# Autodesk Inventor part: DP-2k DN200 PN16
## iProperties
Created: 2009-08
Part Number: DP-2k DN200 PN16
Document SubType Name: Modelowanie
Designer: Marcin Pyzik
Author: Marcin Pyzik
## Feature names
1. Wyciągnięcie proste1 [Extrusion]
2. Faza1 [Chamfer]
3. Bryła wyprowadzona1 [Tagging]
